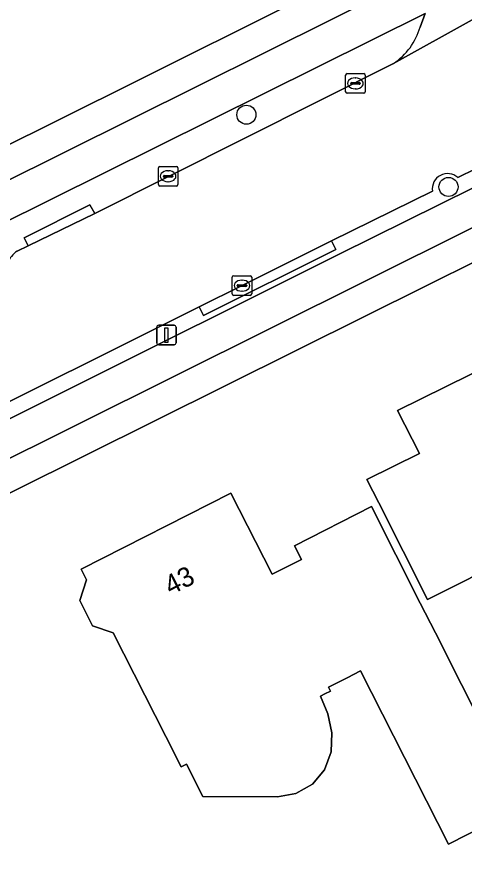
# Model space of a CAD drawing. Extents: x 157320 to 158835, y 386650 to 388491.
# Drawn here: x 157534.2 to 157557.12, y 387592.43 to 387636.29 of the extents above; entities that cross this region are included whole.
import ezdxf

# ---------------------------------------------------------------- set-up
doc = ezdxf.new("R2010")
doc.units = 0
for name, color, linetype in [('IMGEO_Berm_open', 7, 'Continuous'), ('IMGEO_Boom', 7, 'Continuous'), ('IMGEO_Erf', 7, 'Continuous'), ('IMGEO_Fietspad_open', 7, 'Continuous'), ('IMGEO_Kolk', 7, 'Continuous'), ('IMGEO_Lichtmast', 7, 'Continuous'), ('IMGEO_Pand', 7, 'Continuous'), ('IMGEO_Pand_nummerreeks', 7, 'Continuous'), ('IMGEO_Rijbaan_lokaal_open', 7, 'Continuous'), ('IMGEO_Voetpad_open', 7, 'Continuous')]:
    doc.layers.add(name, color=color, linetype=linetype)

msp = doc.modelspace()

# ---------------------------------------------------------------- linework, layer by layer
at = {"layer": 'IMGEO_Berm_open'}
for points in [[(157554.832, 387635.784), (157555.083, 387636.479), (157533.2, 387625.612), (157523.314, 387620.754), (157507.194, 387612.771), (157505.833, 387612.097), (157506.187, 387611.363), (157507.717, 387612.119), (157517.211, 387616.81), (157521.759, 387619.08), (157523.243, 387619.86)], [(157534.197, 387624.317), (157534.761, 387624.579), (157534.554, 387624.987), (157537.92, 387626.678), (157538.168, 387626.233), (157553.464, 387633.91)], [(157550.724, 387624.167), (157560.959, 387629.234), (157560.593, 387629.947), (157560.385, 387629.858), (157556.766, 387628.078)], [(157555.461, 387627.386), (157550.286, 387624.845), (157550.512, 387624.392), (157543.737, 387621.02), (157543.521, 387621.465), (157530.341, 387614.895)], [(157529.042, 387614.221), (157521.536, 387610.5), (157512.562, 387606.067), (157501.251, 387600.479), (157500, 387599.852), (157498.085, 387598.904), (157498.446, 387598.178), (157500, 387598.947), (157513.079, 387605.421), (157521.688, 387609.683), (157550.724, 387624.167)]]:
    msp.add_lwpolyline(points, dxfattribs=at)
for points in [[(157538.168, 387626.233), (157537.92, 387626.678), (157534.554, 387624.987), (157534.761, 387624.579)], [(157550.512, 387624.392), (157550.286, 387624.845), (157545.712, 387622.545), (157543.521, 387621.465), (157543.737, 387621.02)]]:
    msp.add_lwpolyline(points, close=True, dxfattribs=at)
for centre, radius, start, end in [((157551.585, 387636.718), 3.379, 303.7883, 343.9536), ((157556.239, 387627.495), 0.786, 47.9139, 187.9573), ((157534.938, 387623.235), 1.312, 124.4001, 159.5455)]:
    msp.add_arc(centre, radius, start, end, dxfattribs=at)
at = {"layer": 'IMGEO_Boom'}
for centre in [(157545.936, 387631.296), (157556.287, 387627.598)]:
    msp.add_circle(centre, 0.489, dxfattribs=at)
at = {"layer": 'IMGEO_Erf'}
for points in [[(157504.981, 387615.535), (157517.556, 387621.762), (157535.44, 387630.592), (157553.174, 387639.447)], [(157615.927, 387559.839), (157611.374, 387562.193), (157605.111, 387565.47), (157601.282, 387567.578), (157591.851, 387572.768), (157565.719, 387617.13), (157560.875, 387625.389), (157552.086, 387621.025), (157523.261, 387606.675), (157516.796, 387603.48), (157517.241, 387602.962), (157517.52, 387602.638), (157562.957, 387552.907), (157563.938, 387551.687), (157578.677, 387533.351), (157589.022, 387521.485)], [(157560.083, 387595.885), (157556.28, 387593.957), (157551.784, 387602.821), (157551.096, 387602.472), (157550.146, 387601.99), (157550.248, 387601.791), (157549.952, 387601.641), (157549.725, 387601.526), (157550.102, 387600.623), (157550.305, 387599.651), (157550.275, 387598.68), (157549.943, 387597.761), (157549.328, 387597.024), (157548.464, 387596.541), (157547.524, 387596.377), (157543.7, 387596.398), (157542.867, 387598.048), (157542.6, 387597.912), (157541.815, 387599.459), (157539.118, 387604.778), (157538.059, 387605.124), (157537.402, 387606.419), (157537.75, 387607.483), (157537.473, 387608.031), (157545.143, 387611.921), (157547.25, 387607.768), (157548.753, 387608.53), (157548.397, 387609.232), (157552.339, 387611.232), (157554.842, 387606.298), (157555.619, 387604.766), (157559.591, 387596.871)]]:
    msp.add_lwpolyline(points, dxfattribs=at)
msp.add_lwpolyline([(157555.215, 387606.486), (157552.713, 387611.421), (157552.103, 387612.624), (157554.807, 387613.947), (157553.681, 387616.145), (157559.863, 387619.203), (157564.017, 387610.895)], close=True, dxfattribs=at)
at = {"layer": 'IMGEO_Fietspad_open'}
msp.add_lwpolyline([(157553.691, 387637.874), (157536.678, 387629.402), (157522.765, 387622.48), (157506.043, 387614.209), (157505.035, 387613.71), (157505.833, 387612.097), (157507.194, 387612.771), (157523.314, 387620.754), (157533.2, 387625.612), (157555.083, 387636.479)], dxfattribs=at)
msp.add_lwpolyline([(157562.729, 387628.115), (157560.959, 387629.234), (157550.724, 387624.167), (157521.688, 387609.683), (157513.079, 387605.421), (157500, 387598.947), (157498.446, 387598.178), (157498.085, 387598.904), (157492.946, 387596.358), (157493.349, 387595.59), (157485.776, 387591.849), (157486.565, 387590.235), (157500, 387596.925), (157501.066, 387597.456), (157514.23, 387603.984), (157522.473, 387608.072), (157552.115, 387622.822)], close=True, dxfattribs=at)
at = {"layer": 'IMGEO_Kolk'}
for p, q in [((157551.019, 387632.473), (157551.019, 387633.325)), ((157551.094, 387633.399), (157551.946, 387633.399)), ((157551.507, 387633.179), (157551.532, 387633.179)), ((157552.02, 387633.325), (157552.02, 387632.473)), ((157551.278, 387632.893), (157551.278, 387632.905)), ((157551.716, 387632.856), (157551.318, 387632.856)), ((157551.321, 387632.942), (157551.719, 387632.942)), ((157551.53, 387632.619), (157551.505, 387632.619)), ((157551.762, 387632.905), (157551.762, 387632.893)), ((157551.946, 387632.399), (157551.094, 387632.399)), ((157541.428, 387627.72), (157541.428, 387628.572)), ((157541.503, 387628.646), (157542.355, 387628.646)), ((157541.916, 387628.426), (157541.941, 387628.426)), ((157542.429, 387628.572), (157542.429, 387627.72)), ((157541.687, 387628.14), (157541.687, 387628.152)), ((157542.125, 387628.103), (157541.727, 387628.103)), ((157541.73, 387628.189), (157542.128, 387628.189)), ((157541.939, 387627.866), (157541.914, 387627.866)), ((157542.171, 387628.152), (157542.171, 387628.14)), ((157542.355, 387627.646), (157541.503, 387627.646)), ((157545.21, 387622.12), (157545.21, 387622.972)), ((157545.285, 387623.046), (157546.137, 387623.046)), ((157546.211, 387622.972), (157546.211, 387622.12)), ((157545.469, 387622.54), (157545.469, 387622.552)), ((157545.512, 387622.589), (157545.91, 387622.589)), ((157545.698, 387622.826), (157545.723, 387622.826)), ((157545.953, 387622.552), (157545.953, 387622.54)), ((157545.907, 387622.503), (157545.509, 387622.503)), ((157545.721, 387622.266), (157545.696, 387622.266)), ((157546.137, 387622.046), (157545.285, 387622.046))]:
    msp.add_line(p, q, dxfattribs=at)
for points in [[(157551.019, 387632.473), (157551.019, 387633.325)], [(157551.094, 387633.399), (157551.946, 387633.399)], [(157552.02, 387633.325), (157552.02, 387632.473)], [(157551.946, 387632.399), (157551.094, 387632.399)], [(157541.428, 387627.72), (157541.428, 387628.572)], [(157541.503, 387628.646), (157542.355, 387628.646)], [(157542.429, 387628.572), (157542.429, 387627.72)], [(157542.355, 387627.646), (157541.503, 387627.646)], [(157545.21, 387622.12), (157545.21, 387622.972)], [(157545.285, 387623.046), (157546.137, 387623.046)], [(157546.211, 387622.972), (157546.211, 387622.12)], [(157546.137, 387622.046), (157545.285, 387622.046)]]:
    msp.add_lwpolyline(points, dxfattribs=at)
for centre, radius, start, end in [((157551.096, 387633.323), 0.0765, 91.552, 178.448), ((157551.096, 387633.323), 0.0765, 91.552, 178.448), ((157551.944, 387633.323), 0.0765, 1.552, 88.448), ((157551.944, 387633.323), 0.0765, 1.552, 88.448), ((157551.318, 387632.902), 0.0403, 85.8775, 175.7526), ((157551.315, 387632.892), 0.0366, 178.938, 274.7102), ((157551.719, 387632.899), 0.043, 264.8664, 352.4533), ((157551.723, 387632.904), 0.0386, 1.7309, 96.639), ((157551.096, 387632.475), 0.0765, 181.552, 268.448), ((157551.096, 387632.475), 0.0765, 181.552, 268.448), ((157551.944, 387632.475), 0.0765, 271.552, 358.448), ((157551.944, 387632.475), 0.0765, 271.552, 358.448), ((157541.505, 387628.57), 0.0765, 91.552, 178.448), ((157541.505, 387628.57), 0.0765, 91.552, 178.448), ((157542.353, 387628.57), 0.0765, 1.552, 88.448), ((157542.353, 387628.57), 0.0765, 1.552, 88.448), ((157541.727, 387628.149), 0.0403, 85.8775, 175.7526), ((157541.724, 387628.139), 0.0366, 178.938, 274.7102), ((157542.128, 387628.146), 0.043, 264.8664, 352.4533), ((157542.132, 387628.151), 0.0386, 1.7309, 96.639), ((157541.505, 387627.722), 0.0765, 181.552, 268.448), ((157541.505, 387627.722), 0.0765, 181.552, 268.448), ((157542.353, 387627.722), 0.0765, 271.552, 358.448), ((157542.353, 387627.722), 0.0765, 271.552, 358.448), ((157545.287, 387622.97), 0.0765, 91.552, 178.448), ((157545.287, 387622.97), 0.0765, 91.552, 178.448), ((157546.135, 387622.97), 0.0765, 1.552, 88.448), ((157546.135, 387622.97), 0.0765, 1.552, 88.448), ((157545.509, 387622.549), 0.0403, 85.8775, 175.7526), ((157545.506, 387622.539), 0.0366, 178.938, 274.7102), ((157545.91, 387622.546), 0.043, 264.8664, 352.4533), ((157545.914, 387622.551), 0.0386, 1.7309, 96.639), ((157545.287, 387622.122), 0.0765, 181.552, 268.448), ((157545.287, 387622.122), 0.0765, 181.552, 268.448), ((157546.135, 387622.122), 0.0765, 271.552, 358.448), ((157546.135, 387622.122), 0.0765, 271.552, 358.448)]:
    msp.add_arc(centre, radius, start, end, dxfattribs=at)
for centre, major_axis, ratio, start_param, end_param in [((157551.506, 387632.899), (-0.387, 0.002), 0.722429, 4.712389, 7.853982), ((157551.531, 387632.899), (-0.39, 0.002), 0.717154, 1.570796, 4.712389), ((157541.915, 387628.146), (-0.387, 0.002), 0.722429, 4.712389, 7.853982), ((157541.94, 387628.146), (-0.39, 0.002), 0.717154, 1.570796, 4.712389), ((157545.697, 387622.546), (-0.387, 0.002), 0.722429, 4.712389, 7.853982), ((157545.722, 387622.546), (-0.39, 0.002), 0.717154, 1.570796, 4.712389)]:
    msp.add_ellipse(centre, major_axis=major_axis, ratio=ratio, start_param=start_param, end_param=end_param, dxfattribs=at)
at = {"layer": 'IMGEO_Lichtmast'}
for p, q in [((157541.346, 387619.616), (157541.346, 387620.416)), ((157541.346, 387620.416), (157541.346, 387619.616)), ((157541.446, 387620.516), (157542.236, 387620.516)), ((157542.236, 387620.516), (157541.446, 387620.516)), ((157542.336, 387620.416), (157542.336, 387619.616)), ((157542.336, 387619.616), (157542.336, 387620.416)), ((157542.236, 387619.516), (157541.446, 387619.516)), ((157541.446, 387619.516), (157542.236, 387619.516))]:
    msp.add_line(p, q, dxfattribs=at)
msp.add_lwpolyline([(157541.766, 387620.391), (157541.916, 387620.391), (157541.916, 387619.641), (157541.766, 387619.641), (157541.766, 387620.391)], dxfattribs=at)
for centre, start, end in [((157541.446, 387620.416), 90, 180), ((157541.446, 387620.416), 90, 180), ((157542.236, 387620.416), 0, 90), ((157542.236, 387620.416), 360, 90), ((157541.446, 387619.616), 180, 270), ((157541.446, 387619.616), 180, 270), ((157542.236, 387619.616), 270, 0), ((157542.236, 387619.616), 270, 0)]:
    msp.add_arc(centre, 0.1, start, end, dxfattribs=at)
at = {"layer": 'IMGEO_Pand'}
msp.add_lwpolyline([(157552.713, 387611.421), (157555.215, 387606.486), (157564.017, 387610.895), (157559.863, 387619.203), (157553.681, 387616.145), (157554.807, 387613.947), (157552.103, 387612.624)], close=True, dxfattribs=at)
msp.add_lwpolyline([(157559.591, 387596.871), (157555.619, 387604.766), (157554.842, 387606.298), (157552.339, 387611.232), (157548.397, 387609.232), (157548.753, 387608.53), (157547.25, 387607.768), (157545.143, 387611.921), (157537.473, 387608.031), (157537.75, 387607.483), (157537.402, 387606.419), (157538.059, 387605.124), (157539.118, 387604.778), (157541.815, 387599.459), (157542.6, 387597.912), (157542.867, 387598.048), (157543.7, 387596.398), (157547.524, 387596.377), (157548.464, 387596.541), (157549.328, 387597.024), (157549.943, 387597.761), (157550.275, 387598.68), (157550.305, 387599.651), (157550.102, 387600.623), (157549.725, 387601.526), (157549.952, 387601.641), (157550.248, 387601.791), (157550.146, 387601.99), (157551.096, 387602.472), (157551.784, 387602.821), (157556.28, 387593.957), (157560.083, 387595.885)], dxfattribs=at)
at = {"layer": 'IMGEO_Rijbaan_lokaal_open'}
for points in [[(157571.737, 387643.997), (157570.832, 387643.519), (157569.732, 387642.953), (157553.464, 387633.91), (157538.168, 387626.233), (157534.761, 387624.579), (157534.197, 387624.317)], [(157553.464, 387633.91), (157569.732, 387642.953)], [(157556.766, 387628.078), (157560.385, 387629.858), (157560.593, 387629.947), (157569.341, 387634.325), (157574.054, 387636.702)], [(157555.083, 387636.479), (157554.832, 387635.784)], [(157530.341, 387614.895), (157543.521, 387621.465), (157545.712, 387622.545), (157550.286, 387624.845), (157555.461, 387627.386)]]:
    msp.add_lwpolyline(points, dxfattribs=at)
for centre, radius, start, end in [((157551.585, 387636.718), 3.379, 303.7883, 343.9536), ((157556.239, 387627.495), 0.786, 47.9139, 187.9573), ((157534.938, 387623.235), 1.312, 124.4001, 159.5455)]:
    msp.add_arc(centre, radius, start, end, dxfattribs=at)
at = {"layer": 'IMGEO_Voetpad_open'}
for points in [[(157556.132, 387640.802), (157556.141, 387640.867), (157556.148, 387640.932), (157553.174, 387639.447), (157535.44, 387630.592), (157517.556, 387621.762), (157504.981, 387615.535), (157503.32, 387614.713), (157504.06, 387613.232), (157505.035, 387613.71), (157506.043, 387614.209), (157522.765, 387622.48), (157536.678, 387629.402), (157553.691, 387637.874)], [(157502.531, 387596.428), (157515.247, 387602.714), (157516.796, 387603.48), (157523.261, 387606.675), (157552.086, 387621.025), (157560.875, 387625.389), (157564.234, 387627.164), (157562.729, 387628.115), (157552.115, 387622.822), (157522.473, 387608.072), (157514.23, 387603.984), (157501.066, 387597.456)]]:
    msp.add_lwpolyline(points, dxfattribs=at)

# ---------------------------------------------------------------- texts
at = {"layer": 'IMGEO_Pand_nummerreeks'}
msp.add_text('43', height=1, rotation=26.8946, dxfattribs=at).set_placement((157542.055, 387606.677))

doc.saveas('drawing.dxf')
